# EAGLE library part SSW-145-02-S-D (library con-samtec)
THROUGH-HOLE .025" SQ POST SOCKET Source: Samtec SSW.pdf
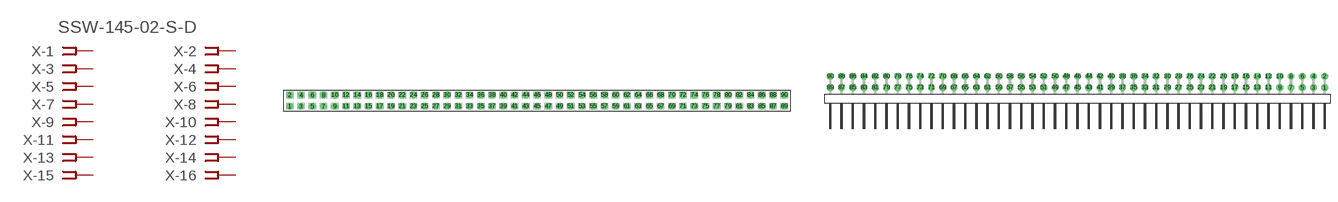
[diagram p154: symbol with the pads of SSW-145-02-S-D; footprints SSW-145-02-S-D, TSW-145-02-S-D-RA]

Designator prefix X; gates -1=FPINV -2=FPIN -3=FPIN -4=FPIN -5=FPIN -6=FPIN -7=FPIN -8=FPIN -9=FPIN -10=FPIN -11=FPIN -12=FPIN -13=FPIN -14=FPIN -15=FPIN -16=FPIN -17=FPIN -18=FPIN -19=FPIN -20=FPIN -21=FPIN -22=FPIN -23=FPIN -24=FPIN -25=FPIN -26=FPIN -27=FPIN -28=FPIN -29=FPIN -30=FPIN -31=FPIN -32=FPIN -33=FPIN -34=FPIN -35=FPIN -36=FPIN -37=FPIN -38=FPIN -39=FPIN -40=FPIN -41=FPIN -42=FPIN -43=FPIN -44=FPIN -45=FPIN -46=FPIN -47=FPIN -48=FPIN -49=FPIN -50=FPIN -51=FPIN -52=FPIN -53=FPIN -54=FPIN -55=FPIN -56=FPIN -57=FPIN -58=FPIN -59=FPIN -60=FPIN -61=FPIN -62=FPIN -63=FPIN -64=FPIN -65=FPIN -66=FPIN -67=FPIN -68=FPIN -69=FPIN -70=FPIN -71=FPIN -72=FPIN -73=FPIN -74=FPIN -75=FPIN -76=FPIN -77=FPIN -78=FPIN -79=FPIN -80=FPIN -81=FPIN -82=FPIN -83=FPIN -84=FPIN -85=FPIN -86=FPIN -87=FPIN -88=FPIN -89=FPIN -90=FPIN

## SSW-145-02-S-D (MPN: SSW-145-02-S-D; OC_FARNELL: unknown; OC_NEWARK: 12P0013)  [SSW-145-02-S-D]
1  -1:1  pas
2  -2:1  pas
3  -3:1  pas
4  -4:1  pas
5  -5:1  pas
6  -6:1  pas
7  -7:1  pas
8  -8:1  pas
9  -9:1  pas
10  -10:1  pas
11  -11:1  pas
12  -12:1  pas
13  -13:1  pas
14  -14:1  pas
15  -15:1  pas
16  -16:1  pas
17  -17:1  pas
18  -18:1  pas
19  -19:1  pas
20  -20:1  pas
21  -21:1  pas
22  -22:1  pas
23  -23:1  pas
24  -24:1  pas
25  -25:1  pas
26  -26:1  pas
27  -27:1  pas
28  -28:1  pas
29  -29:1  pas
30  -30:1  pas
31  -31:1  pas
32  -32:1  pas
33  -33:1  pas
34  -34:1  pas
35  -35:1  pas
36  -36:1  pas
37  -37:1  pas
38  -38:1  pas
39  -39:1  pas
40  -40:1  pas
41  -41:1  pas
42  -42:1  pas
43  -43:1  pas
44  -44:1  pas
45  -45:1  pas
46  -46:1  pas
47  -47:1  pas
48  -48:1  pas
49  -49:1  pas
50  -50:1  pas
51  -51:1  pas
52  -52:1  pas
53  -53:1  pas
54  -54:1  pas
55  -55:1  pas
56  -56:1  pas
57  -57:1  pas
58  -58:1  pas
59  -59:1  pas
60  -60:1  pas
61  -61:1  pas
62  -62:1  pas
63  -63:1  pas
64  -64:1  pas
65  -65:1  pas
66  -66:1  pas
67  -67:1  pas
68  -68:1  pas
69  -69:1  pas
70  -70:1  pas
71  -71:1  pas
72  -72:1  pas
73  -73:1  pas
74  -74:1  pas
75  -75:1  pas
76  -76:1  pas
77  -77:1  pas
78  -78:1  pas
79  -79:1  pas
80  -80:1  pas
81  -81:1  pas
82  -82:1  pas
83  -83:1  pas
84  -84:1  pas
85  -85:1  pas
86  -86:1  pas
87  -87:1  pas
88  -88:1  pas
89  -89:1  pas
90  -90:1  pas

## SSW-145-02-S-D-RA (MPN: SSW-145-02-S-D-RA; OC_FARNELL: unknown; OC_NEWARK: 12P0014)  [TSW-145-02-S-D-RA]
Pads as for SSW-145-02-S-D

## Footprint SSW-145-02-S-D (pad centres in mm)
THROUGH-HOLE .025" SQ POST SOCKET Source: Samtec SSW.pdf
drill 1 pad 1.5 octagon: 1 -55.88,-1.27; 2 -55.88,1.27; 3 -53.34,-1.27; 4 -53.34,1.27; 5 -50.8,-1.27; 6 -50.8,1.27; 7 -48.26,-1.27; 8 -48.26,1.27; 9 -45.72,-1.27; 10 -45.72,1.27; 11 -43.18,-1.27; 12 -43.18,1.27; 13 -40.64,-1.27; 14 -40.64,1.27; 15 -38.1,-1.27; 16 -38.1,1.27; 17 -35.56,-1.27; 18 -35.56,1.27; 19 -33.02,-1.27; 20 -33.02,1.27; 21 -30.48,-1.27; 22 -30.48,1.27; 23 -27.94,-1.27; 24 -27.94,1.27; 25 -25.4,-1.27; 26 -25.4,1.27; 27 -22.86,-1.27; 28 -22.86,1.27; 29 -20.32,-1.27; 30 -20.32,1.27; 31 -17.78,-1.27; 32 -17.78,1.27; 33 -15.24,-1.27; 34 -15.24,1.27; 35 -12.7,-1.27; 36 -12.7,1.27; 37 -10.16,-1.27; 38 -10.16,1.27; 39 -7.62,-1.27; 40 -7.62,1.27; 41 -5.08,-1.27; 42 -5.08,1.27; 43 -2.54,-1.27; 44 -2.54,1.27; 45 0,-1.27; 46 0,1.27; 47 2.54,-1.27; 48 2.54,1.27; 49 5.08,-1.27; 50 5.08,1.27; 51 7.62,-1.27; 52 7.62,1.27; 53 10.16,-1.27; 54 10.16,1.27; 55 12.7,-1.27; 56 12.7,1.27; 57 15.24,-1.27; 58 15.24,1.27; 59 17.78,-1.27; 60 17.78,1.27; 61 20.32,-1.27; 62 20.32,1.27; 63 22.86,-1.27; 64 22.86,1.27; 65 25.4,-1.27; 66 25.4,1.27; 67 27.94,-1.27; 68 27.94,1.27; 69 30.48,-1.27; 70 30.48,1.27; 71 33.02,-1.27; 72 33.02,1.27; 73 35.56,-1.27; 74 35.56,1.27; 75 38.1,-1.27; 76 38.1,1.27; 77 40.64,-1.27; 78 40.64,1.27; 79 43.18,-1.27; 80 43.18,1.27; 81 45.72,-1.27; 82 45.72,1.27; 83 48.26,-1.27; 84 48.26,1.27; 85 50.8,-1.27; 86 50.8,1.27; 87 53.34,-1.27; 88 53.34,1.27; 89 55.88,-1.27; 90 55.88,1.27

## Footprint TSW-145-02-S-D-RA (pad centres in mm)
THROUGH-HOLE .025" SQ POST HEADER Source: Samtec TSW.pdf
drill 1 pad 1.5 octagon: 1 55.88,1.524; 2 55.88,4.064; 3 53.34,1.524; 4 53.34,4.064; 5 50.8,1.524; 6 50.8,4.064; 7 48.26,1.524; 8 48.26,4.064; 9 45.72,1.524; 10 45.72,4.064; 11 43.18,1.524; 12 43.18,4.064; 13 40.64,1.524; 14 40.64,4.064; 15 38.1,1.524; 16 38.1,4.064; 17 35.56,1.524; 18 35.56,4.064; 19 33.02,1.524; 20 33.02,4.064; 21 30.48,1.524; 22 30.48,4.064; 23 27.94,1.524; 24 27.94,4.064; 25 25.4,1.524; 26 25.4,4.064; 27 22.86,1.524; 28 22.86,4.064; 29 20.32,1.524; 30 20.32,4.064; 31 17.78,1.524; 32 17.78,4.064; 33 15.24,1.524; 34 15.24,4.064; 35 12.7,1.524; 36 12.7,4.064; 37 10.16,1.524; 38 10.16,4.064; 39 7.62,1.524; 40 7.62,4.064; 41 5.08,1.524; 42 5.08,4.064; 43 2.54,1.524; 44 2.54,4.064; 45 0,1.524; 46 0,4.064; 47 -2.54,1.524; 48 -2.54,4.064; 49 -5.08,1.524; 50 -5.08,4.064; 51 -7.62,1.524; 52 -7.62,4.064; 53 -10.16,1.524; 54 -10.16,4.064; 55 -12.7,1.524; 56 -12.7,4.064; 57 -15.24,1.524; 58 -15.24,4.064; 59 -17.78,1.524; 60 -17.78,4.064; 61 -20.32,1.524; 62 -20.32,4.064; 63 -22.86,1.524; 64 -22.86,4.064; 65 -25.4,1.524; 66 -25.4,4.064; 67 -27.94,1.524; 68 -27.94,4.064; 69 -30.48,1.524; 70 -30.48,4.064; 71 -33.02,1.524; 72 -33.02,4.064; 73 -35.56,1.524; 74 -35.56,4.064; 75 -38.1,1.524; 76 -38.1,4.064; 77 -40.64,1.524; 78 -40.64,4.064; 79 -43.18,1.524; 80 -43.18,4.064; 81 -45.72,1.524; 82 -45.72,4.064; 83 -48.26,1.524; 84 -48.26,4.064; 85 -50.8,1.524; 86 -50.8,4.064; 87 -53.34,1.524; 88 -53.34,4.064; 89 -55.88,1.524; 90 -55.88,4.064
